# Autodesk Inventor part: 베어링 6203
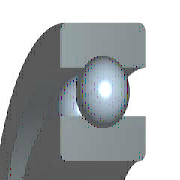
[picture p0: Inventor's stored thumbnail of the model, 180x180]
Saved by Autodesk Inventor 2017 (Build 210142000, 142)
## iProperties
IsCustomPart: 0
Created: 2016-04
Part Number: 베어링 6203
Material: 강철, 연강
Description: 깊은 그루브 볼 베어링
Document SubType Name: Modeling
Standard: KS B 2023
Designer: mdu
Standards Organization: KS
Language: ko-KR
Size Designation: 6203 - 17 x 40 x 12
Categories: <MemberInstance><Categories><Category DisplayName="샤프트 부품" InternalName="7f7aeb1f-a693-4053-b835-cee3144e0d98" Mnemonic="SHFT"><Category DisplayName="베어링" Inter
Density: 7.86 g/cm^3
Mass: 64.9809 g
Surface Area: 64.3582 cm^2
Volume: 8.26729 cm^3
Appearance: 노란색
Author: mdu
Revision Number: 1
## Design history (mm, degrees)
sketch "스케치" dims "d0" = 5.98 (= -0.26 x WD + 0.26 x BD)
  geometry: L1 (3.01, 14.25)-(8.99, 14.25); L2 (6, 14.25)-(6, 11.26); L3 (6, 14.25)-(6, 17.24); L4 (3.778, 12.249)-(0, 12.249); L5 (0, 8.5)-(12, 8.5); L6 (3.778, 16.251)-(0, 16.251); L7 (0, 20)-(12, 20); L8 (12, 8.5)-(12, 12.249); L9 (8.222, 12.249)-(12, 12.249); L10 (8.222, 16.251)-(12, 16.251); L11 (12, 20)-(12, 16.251); L12 (-1.4, 0)-(8.4, 0) reference; L13 (0, -0.3)-(0, 5.3) reference
  constraints: 22 end point, 4 point on line, 2 collinear, 2 perpendicular, 2 symmetric about line, 1 midpoint, 1 parallel, 14 other
  dimensions: "d9" = 17 diameter of L5 L12 (= WD); "d11" = 40 diameter of L7 L12 (= BD); "d12" = 12 distance between parallel lines of L8 L13 (= KB); "d13" = 24.498 diameter of L9 L12 (= 0.326 x BD + 0.674 x WD)
revolve "본체" stored, may be unused: angle "d6" = 90 deg
revolve "볼" stored, may be unused: angle "d7" = 90 deg
pattern_circular "IDS_ARRAYBALL[SIMPL:T]" dims angle "d3" = 360 deg
body "Solid1"
fillet "모깎기1" dims "d1" = 0.6 (= KRS)
other parameters: "WD" = 17 [user parameter; used in 5 equation terms], "BD" = 40 [user parameter; used in 5 equation terms], "KB" = 12 [user parameter; used in 1 equation term], "KRS" = 0.6 [user parameter; used in 1 equation term], "d4" = 0, "d5" = 0, "d8" = 0, "d14" = 0, "d15" = 0, "BBA" = 0 [user parameter], "BC0" = 4750000 [user parameter], "BC" = 9560000 [user parameter], "WR" = 8.5 (= 0.5 x WD) [user parameter]
